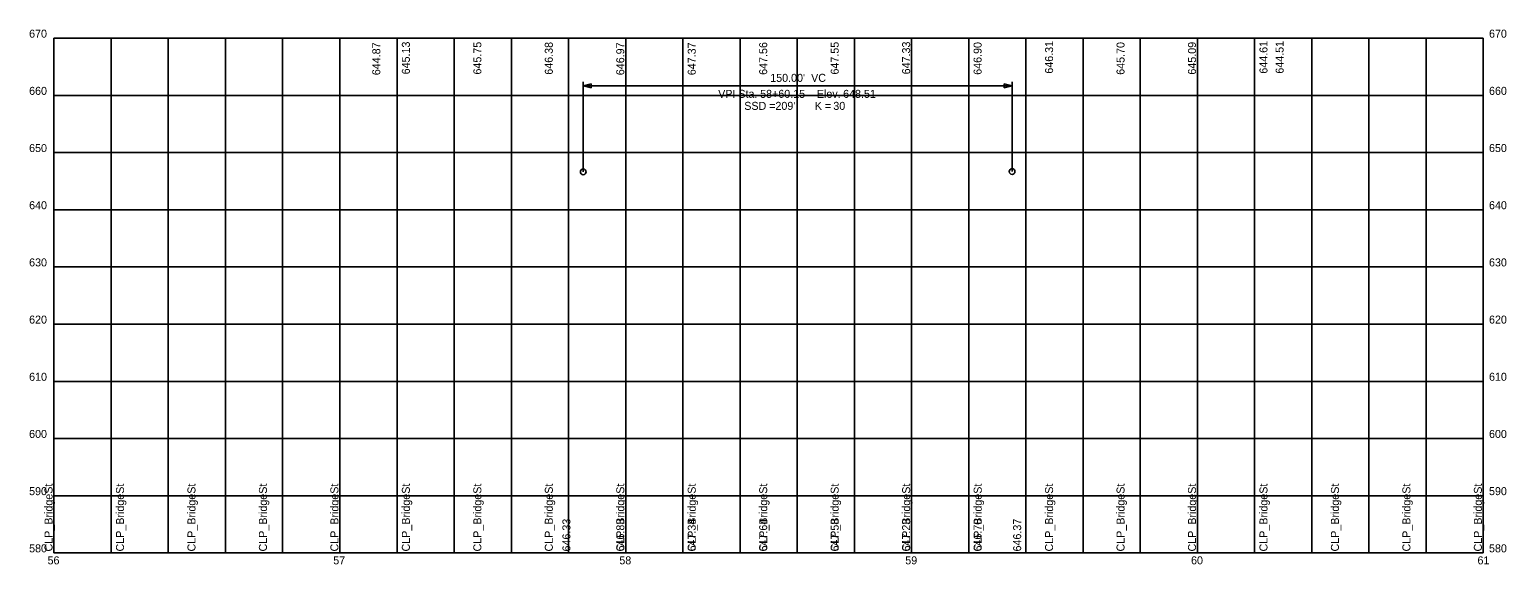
# Model space of a CAD drawing. Extents: x 92 to 609, y 576 to 763.
import ezdxf

# ---------------------------------------------------------------- set-up
doc = ezdxf.new("R2010")
doc.units = 0
for name, color, linetype in [('Default', 7, 'Continuous'), ('PF_P_Sta_Elev_Text', 7, 'Continuous'), ('PF_P_Text_Curve', 7, 'Continuous'), ('PF_P_Text_Strip_Grades_20', 7, 'Continuous'), ('PF_X_Text_Strip_Grade', 7, 'Continuous'), ('SH_Major_Grid_Line', 7, 'Continuous')]:
    doc.layers.add(name, color=color, linetype=linetype)

msp = doc.modelspace()

# ---------------------------------------------------------------- linework, layer by layer
at = {"layer": 'PF_P_Text_Curve'}
for p, q in [((285.7, 713.27), (285.7, 744.75)), ((435.7, 713.35), (435.7, 744.75)), ((285.7, 743.45), (285.7, 743.25)), ((285.7, 743.35), (435.7, 743.35)), ((435.7, 743.25), (435.7, 743.45))]:
    msp.add_line(p, q, dxfattribs=at)
for points in [[(285.7, 743.35), (288.42, 744.03), (288.42, 742.67)], [(435.7, 743.35), (432.98, 742.67), (432.98, 744.03)]]:
    msp.add_lwpolyline(points, close=True, dxfattribs=at)
for centre in [(285.7, 713.27), (435.7, 713.35)]:
    msp.add_circle(centre, 1, dxfattribs=at)
at = {"layer": 'SH_Major_Grid_Line'}
for p, q in [((100.55, 760), (600.55, 760)), ((100.55, 580), (100.55, 760)), ((100.55, 580), (100.55, 760)), ((120.55, 580), (120.55, 760)), ((140.55, 580), (140.55, 760)), ((160.55, 580), (160.55, 760)), ((180.55, 580), (180.55, 760)), ((200.55, 580), (200.55, 760)), ((220.55, 580), (220.55, 760)), ((240.55, 580), (240.55, 760)), ((260.55, 580), (260.55, 760)), ((280.55, 580), (280.55, 760)), ((300.55, 580), (300.55, 760)), ((320.55, 580), (320.55, 760)), ((340.55, 580), (340.55, 760)), ((360.55, 580), (360.55, 760)), ((380.55, 580), (380.55, 760)), ((400.55, 580), (400.55, 760)), ((420.55, 580), (420.55, 760)), ((440.55, 580), (440.55, 760)), ((460.55, 580), (460.55, 760)), ((480.55, 580), (480.55, 760)), ((500.55, 580), (500.55, 760)), ((520.55, 580), (520.55, 760)), ((540.55, 580), (540.55, 760)), ((560.55, 580), (560.55, 760)), ((580.55, 580), (580.55, 760)), ((600.55, 580), (600.55, 760)), ((100.55, 740), (600.55, 740)), ((100.55, 720), (600.55, 720)), ((100.55, 700), (600.55, 700)), ((100.55, 680), (600.55, 680)), ((100.55, 660), (600.55, 660)), ((100.55, 640), (600.55, 640)), ((100.55, 620), (600.55, 620)), ((100.55, 600), (600.55, 600)), ((100.55, 580), (600.55, 580))]:
    msp.add_line(p, q, dxfattribs=at)

# ---------------------------------------------------------------- texts
at = {"layer": 'Default'}
for p in [(100.05, 580.5), (125.05, 580.5), (150.05, 580.5), (175.05, 580.5), (200.05, 580.5), (225.05, 580.5), (250.05, 580.5), (275.05, 580.5), (300.05, 580.5), (325.05, 580.5), (350.05, 580.5), (375.05, 580.5), (400.05, 580.5), (425.09, 580.5), (450.05, 580.5), (475.05, 580.5), (500.05, 580.5), (525.05, 580.5), (550.05, 580.5), (575.05, 580.5), (600.05, 580.5)]:
    msp.add_text('CLP_BridgeSt', height=2.8, rotation=90, dxfattribs=at).set_placement(p)
at = {"layer": 'PF_P_Sta_Elev_Text'}
for s, p in [('670', (91.86, 760.2)), ('670', (602.55, 760.2)), ('660', (91.86, 740.2)), ('660', (602.55, 740.2)), ('650', (91.86, 720.2)), ('650', (602.55, 720.2)), ('640', (91.86, 700.2)), ('640', (602.55, 700.2)), ('630', (91.86, 680.2)), ('630', (602.55, 680.2)), ('620', (91.86, 660.2)), ('620', (602.55, 660.2)), ('610', (91.86, 640.2)), ('610', (602.55, 640.2)), ('600', (91.86, 620.2)), ('600', (602.55, 620.2)), ('590', (91.86, 600.2)), ('590', (602.55, 600.2)), ('580', (91.86, 580.2)), ('56', (98.31, 576)), ('57', (198.25, 576)), ('58', (298.33, 576)), ('59', (398.35, 576)), ('60', (498.32, 576)), ('61', (598.52, 576)), ('580', (602.55, 580.2))]:
    msp.add_text(s, height=2.8, dxfattribs=at).set_placement(p)
at = {"layer": 'PF_P_Text_Curve'}
for s, p in [("150.00'", (351.11, 744.75)), (' VC', (364.37, 744.75)), ('VPI Sta. ', (332.9, 739.15)), ('58+60.15', (347.58, 739.15)), ('   Elev. ', (364.3, 739.15)), ('648.51', (376.61, 739.15)), ('SSD = ', (342.03, 734.95)), ("209'", (352.93, 734.95)), ('K = ', (366.7, 734.95)), ('30', (373.18, 734.95))]:
    msp.add_text(s, height=2.8, dxfattribs=at).set_placement(p)
at = {"layer": 'PF_P_Text_Strip_Grades_20'}
for s, p in [('644.87', (214.7, 747.08)), ('645.13', (225.05, 747.37)), ('645.75', (250.05, 747.31)), ('646.38', (275.05, 747.25)), ('646.97', (300.05, 747.08)), ('647.37', (325.05, 747.08)), ('647.56', (350.05, 747.2)), ('647.55', (375.05, 747.31)), ('647.33', (400.05, 747.37)), ('646.90', (425.05, 747.22)), ('646.31', (450.05, 747.61)), ('645.70', (475.05, 747.22)), ('645.09', (500.05, 747.28)), ('644.61', (525.05, 747.61)), ('644.51', (530.7, 747.61))]:
    msp.add_text(s, height=2.8, rotation=90, dxfattribs=at).set_placement(p)
at = {"layer": 'PF_X_Text_Strip_Grade'}
for s, p in [('646.33', (281.21, 580.5)), ('646.83', (300.05, 580.5)), ('647.34', (325.05, 580.5)), ('647.64', (350.05, 580.5)), ('647.58', (375.05, 580.5)), ('647.23', (400.05, 580.5)), ('646.70', (425.05, 580.5)), ('646.37', (438.89, 580.5))]:
    msp.add_text(s, height=2.8, rotation=90, dxfattribs=at).set_placement(p)

doc.saveas('drawing.dxf')
